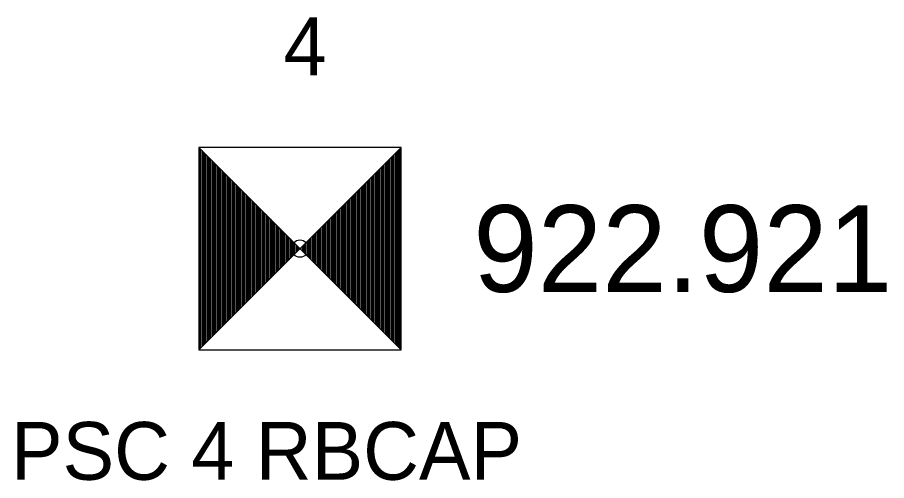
# Model space of a CAD drawing. Extents: x 1393163 to 1398407, y 1072670 to 1074651.
# Drawn here: x 1393163.27 to 1393178.32, y 1073663.93 to 1073671.94 of the extents above; entities that cross this region are included whole.
import ezdxf

# ---------------------------------------------------------------- set-up
doc = ezdxf.new("R2010")
doc.units = 0
for name, color, linetype in [('RD_HC_Survey', 7, 'Continuous'), ('RD_HC_Survey_ELEV', 7, 'Continuous'), ('RD_HC_txCode', 7, 'Continuous'), ('RD_SMD_Locator', 7, 'Continuous')]:
    doc.layers.add(name, color=color, linetype=linetype)

msp = doc.modelspace()

# ---------------------------------------------------------------- linework, layer by layer
at = {"layer": 'RD_HC_Survey'}
for p, q in [((1393166.414, 1073669.693), (1393169.914, 1073666.193)), ((1393169.914, 1073669.693), (1393166.414, 1073666.193)), ((1393166.439, 1073669.668), (1393166.439, 1073666.218)), ((1393166.464, 1073669.643), (1393166.464, 1073666.242)), ((1393166.488, 1073669.619), (1393166.488, 1073666.267)), ((1393166.513, 1073669.594), (1393166.513, 1073666.292)), ((1393166.538, 1073669.569), (1393166.538, 1073666.317)), ((1393169.79, 1073669.569), (1393169.79, 1073666.317)), ((1393169.815, 1073669.594), (1393169.815, 1073666.292)), ((1393169.84, 1073669.619), (1393169.84, 1073666.267)), ((1393169.865, 1073669.643), (1393169.865, 1073666.242)), ((1393169.889, 1073669.668), (1393169.889, 1073666.218)), ((1393166.563, 1073669.544), (1393166.563, 1073666.341)), ((1393166.587, 1073669.52), (1393166.587, 1073666.366)), ((1393166.612, 1073669.495), (1393166.612, 1073666.391)), ((1393166.637, 1073669.47), (1393166.637, 1073666.416)), ((1393166.662, 1073669.445), (1393166.662, 1073666.44)), ((1393166.686, 1073669.421), (1393166.686, 1073666.465)), ((1393169.642, 1073669.421), (1393169.642, 1073666.465)), ((1393169.667, 1073669.445), (1393169.667, 1073666.44)), ((1393169.691, 1073669.47), (1393169.691, 1073666.416)), ((1393169.716, 1073669.495), (1393169.716, 1073666.391)), ((1393169.741, 1073669.52), (1393169.741, 1073666.366)), ((1393169.766, 1073669.544), (1393169.766, 1073666.341)), ((1393166.711, 1073669.396), (1393166.711, 1073666.49)), ((1393166.736, 1073669.371), (1393166.736, 1073666.515)), ((1393166.761, 1073669.346), (1393166.761, 1073666.539)), ((1393166.785, 1073669.322), (1393166.785, 1073666.564)), ((1393166.81, 1073669.297), (1393166.81, 1073666.589)), ((1393166.835, 1073669.272), (1393166.835, 1073666.614)), ((1393169.493, 1073669.272), (1393169.493, 1073666.614)), ((1393169.518, 1073669.297), (1393169.518, 1073666.589)), ((1393169.543, 1073669.322), (1393169.543, 1073666.564)), ((1393169.568, 1073669.346), (1393169.568, 1073666.539)), ((1393169.592, 1073669.371), (1393169.592, 1073666.515)), ((1393169.617, 1073669.396), (1393169.617, 1073666.49)), ((1393166.86, 1073669.247), (1393166.86, 1073666.638)), ((1393166.884, 1073669.223), (1393166.884, 1073666.663)), ((1393166.909, 1073669.198), (1393166.909, 1073666.688)), ((1393166.934, 1073669.173), (1393166.934, 1073666.713)), ((1393166.959, 1073669.148), (1393166.959, 1073666.737)), ((1393166.983, 1073669.124), (1393166.983, 1073666.762)), ((1393169.345, 1073669.124), (1393169.345, 1073666.762)), ((1393169.37, 1073669.148), (1393169.37, 1073666.737)), ((1393169.394, 1073669.173), (1393169.394, 1073666.713)), ((1393169.419, 1073669.198), (1393169.419, 1073666.688)), ((1393169.444, 1073669.223), (1393169.444, 1073666.663)), ((1393169.469, 1073669.247), (1393169.469, 1073666.638)), ((1393167.008, 1073669.099), (1393167.008, 1073666.787)), ((1393167.033, 1073669.074), (1393167.033, 1073666.812)), ((1393167.058, 1073669.049), (1393167.058, 1073666.836)), ((1393167.082, 1073669.025), (1393167.082, 1073666.861)), ((1393167.107, 1073669), (1393167.107, 1073666.886)), ((1393167.132, 1073668.975), (1393167.132, 1073666.911)), ((1393167.157, 1073668.95), (1393167.157, 1073666.935)), ((1393169.172, 1073668.95), (1393169.172, 1073666.935)), ((1393169.196, 1073668.975), (1393169.196, 1073666.911)), ((1393169.221, 1073669), (1393169.221, 1073666.886)), ((1393169.246, 1073669.025), (1393169.246, 1073666.861)), ((1393169.271, 1073669.049), (1393169.271, 1073666.836)), ((1393169.295, 1073669.074), (1393169.295, 1073666.812)), ((1393169.32, 1073669.099), (1393169.32, 1073666.787)), ((1393167.181, 1073668.926), (1393167.181, 1073666.96)), ((1393167.206, 1073668.901), (1393167.206, 1073666.985)), ((1393167.231, 1073668.876), (1393167.231, 1073667.01)), ((1393167.256, 1073668.851), (1393167.256, 1073667.034)), ((1393167.28, 1073668.827), (1393167.28, 1073667.059)), ((1393167.305, 1073668.802), (1393167.305, 1073667.084)), ((1393169.023, 1073668.802), (1393169.023, 1073667.084)), ((1393169.048, 1073668.827), (1393169.048, 1073667.059)), ((1393169.073, 1073668.851), (1393169.073, 1073667.034)), ((1393169.097, 1073668.876), (1393169.097, 1073667.01)), ((1393169.122, 1073668.901), (1393169.122, 1073666.985)), ((1393169.147, 1073668.926), (1393169.147, 1073666.96)), ((1393167.33, 1073668.777), (1393167.33, 1073667.109)), ((1393167.355, 1073668.752), (1393167.355, 1073667.133)), ((1393167.379, 1073668.728), (1393167.379, 1073667.158)), ((1393167.404, 1073668.703), (1393167.404, 1073667.183)), ((1393167.429, 1073668.678), (1393167.429, 1073667.208)), ((1393167.454, 1073668.653), (1393167.454, 1073667.232)), ((1393168.875, 1073668.653), (1393168.875, 1073667.232)), ((1393168.899, 1073668.678), (1393168.899, 1073667.208)), ((1393168.924, 1073668.703), (1393168.924, 1073667.183)), ((1393168.949, 1073668.728), (1393168.949, 1073667.158)), ((1393168.974, 1073668.752), (1393168.974, 1073667.133)), ((1393168.998, 1073668.777), (1393168.998, 1073667.109)), ((1393167.478, 1073668.629), (1393167.478, 1073667.257)), ((1393167.503, 1073668.604), (1393167.503, 1073667.282)), ((1393167.528, 1073668.579), (1393167.528, 1073667.307)), ((1393167.553, 1073668.554), (1393167.553, 1073667.331)), ((1393167.577, 1073668.53), (1393167.577, 1073667.356)), ((1393167.602, 1073668.505), (1393167.602, 1073667.381)), ((1393168.726, 1073668.505), (1393168.726, 1073667.381)), ((1393168.751, 1073668.53), (1393168.751, 1073667.356)), ((1393168.776, 1073668.554), (1393168.776, 1073667.331)), ((1393168.801, 1073668.579), (1393168.801, 1073667.307)), ((1393168.825, 1073668.604), (1393168.825, 1073667.282)), ((1393168.85, 1073668.629), (1393168.85, 1073667.257)), ((1393167.627, 1073668.48), (1393167.627, 1073667.406)), ((1393167.652, 1073668.455), (1393167.652, 1073667.43)), ((1393167.676, 1073668.431), (1393167.676, 1073667.455)), ((1393167.701, 1073668.406), (1393167.701, 1073667.48)), ((1393167.726, 1073668.381), (1393167.726, 1073667.505)), ((1393167.751, 1073668.356), (1393167.751, 1073667.529)), ((1393168.578, 1073668.356), (1393168.578, 1073667.529)), ((1393168.603, 1073668.381), (1393168.603, 1073667.505)), ((1393168.627, 1073668.406), (1393168.627, 1073667.48)), ((1393168.652, 1073668.431), (1393168.652, 1073667.455)), ((1393168.677, 1073668.455), (1393168.677, 1073667.43)), ((1393168.702, 1073668.48), (1393168.702, 1073667.406)), ((1393167.775, 1073668.332), (1393167.775, 1073667.554)), ((1393167.8, 1073668.307), (1393167.8, 1073667.579)), ((1393167.825, 1073668.282), (1393167.825, 1073667.604)), ((1393167.85, 1073668.257), (1393167.85, 1073667.628)), ((1393167.874, 1073668.233), (1393167.874, 1073667.653)), ((1393167.899, 1073668.208), (1393167.899, 1073667.678)), ((1393168.429, 1073668.208), (1393168.429, 1073667.678)), ((1393168.454, 1073668.233), (1393168.454, 1073667.653)), ((1393168.479, 1073668.257), (1393168.479, 1073667.628)), ((1393168.504, 1073668.282), (1393168.504, 1073667.604)), ((1393168.528, 1073668.307), (1393168.528, 1073667.579)), ((1393168.553, 1073668.332), (1393168.553, 1073667.554)), ((1393167.924, 1073668.183), (1393167.924, 1073667.703)), ((1393167.949, 1073668.158), (1393167.949, 1073667.727)), ((1393167.973, 1073668.134), (1393167.973, 1073667.752)), ((1393167.998, 1073668.109), (1393167.998, 1073667.777)), ((1393168.023, 1073668.084), (1393168.023, 1073667.802)), ((1393168.048, 1073668.059), (1393168.048, 1073667.826)), ((1393168.281, 1073668.059), (1393168.281, 1073667.826)), ((1393168.306, 1073668.084), (1393168.306, 1073667.802)), ((1393168.33, 1073668.109), (1393168.33, 1073667.777)), ((1393168.355, 1073668.134), (1393168.355, 1073667.752)), ((1393168.38, 1073668.158), (1393168.38, 1073667.727)), ((1393168.405, 1073668.183), (1393168.405, 1073667.703)), ((1393168.072, 1073668.035), (1393168.072, 1073667.851)), ((1393168.097, 1073668.01), (1393168.097, 1073667.876)), ((1393168.122, 1073667.985), (1393168.122, 1073667.901)), ((1393168.147, 1073667.96), (1393168.147, 1073667.925)), ((1393168.182, 1073667.96), (1393168.182, 1073667.925)), ((1393168.207, 1073667.985), (1393168.207, 1073667.901)), ((1393168.231, 1073668.01), (1393168.231, 1073667.876)), ((1393168.256, 1073668.035), (1393168.256, 1073667.851))]:
    msp.add_line(p, q, dxfattribs=at)
msp.add_lwpolyline([(1393169.914, 1073669.693), (1393166.414, 1073669.693), (1393166.414, 1073666.193), (1393169.914, 1073666.193)], close=True, dxfattribs=at)
at = {"layer": 'RD_SMD_Locator'}
msp.add_circle((1393168.164, 1073667.943), 0.15, dxfattribs=at)

# ---------------------------------------------------------------- texts
at = {"layer": 'RD_HC_Survey_ELEV'}
msp.add_text('922.921', height=1.5, dxfattribs=at).set_placement((1393171.164, 1073667.193))
at = {"layer": 'RD_HC_txCode'}
for s, p in [('4', (1393167.881, 1073670.943)), ('PSC 4 RBCAP', (1393163.164, 1073663.943))]:
    msp.add_text(s, height=1, dxfattribs=at).set_placement(p)

doc.saveas('drawing.dxf')
